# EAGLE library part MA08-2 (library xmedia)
PIN HEADER
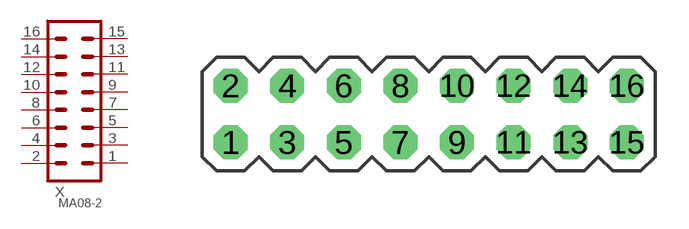
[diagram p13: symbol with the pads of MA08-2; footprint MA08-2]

Designator prefix X

## MA08-2  [MA08-2]
1  1  pas
2  2  pas
3  3  pas
4  4  pas
5  5  pas
6  6  pas
7  7  pas
8  8  pas
9  9  pas
10  10  pas
11  11  pas
12  12  pas
13  13  pas
14  14  pas
15  15  pas
16  16  pas

## Footprint MA08-2 (pad centres in mm)
PIN HEADER
drill 1.016 octagon: 1 -8.89,-1.27; 2 -8.89,1.27; 3 -6.35,-1.27; 4 -6.35,1.27; 5 -3.81,-1.27; 6 -3.81,1.27; 7 -1.27,-1.27; 8 -1.27,1.27; 9 1.27,-1.27; 10 1.27,1.27; 11 3.81,-1.27; 12 3.81,1.27; 13 6.35,-1.27; 14 6.35,1.27; 15 8.89,-1.27; 16 8.89,1.27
